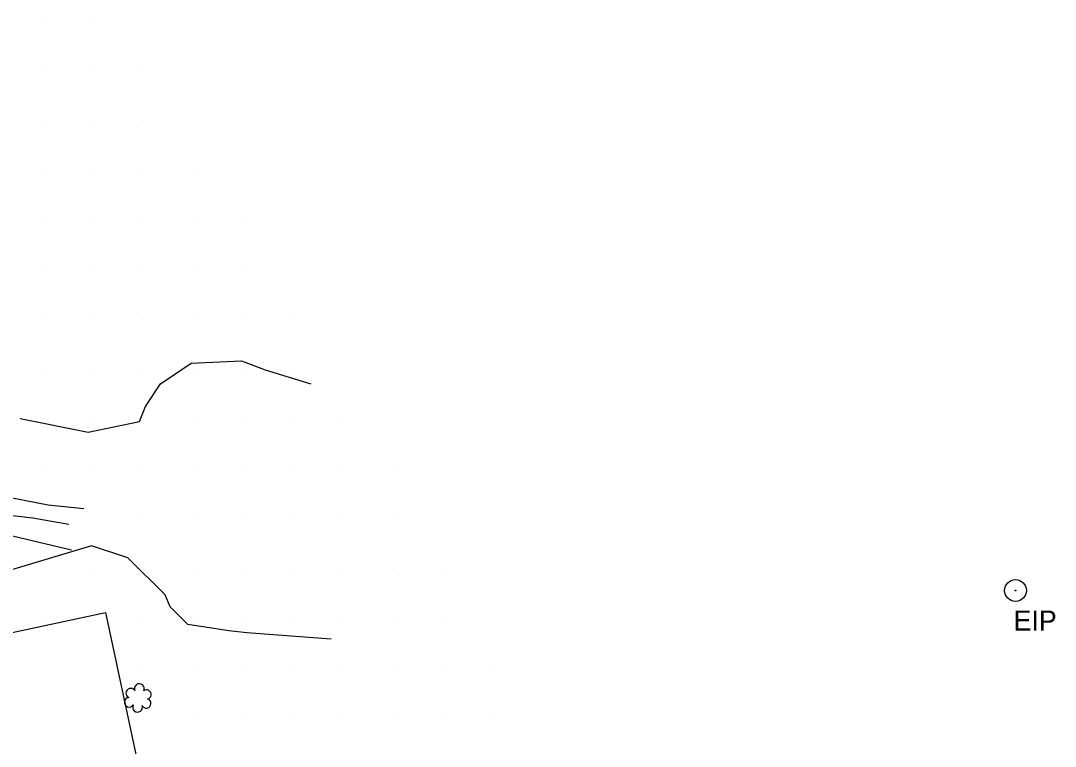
# Model space of a CAD drawing. Extents: x 1548934 to 1561348, y 809680 to 824075.
# Drawn here: x 1552125.4 to 1552333.2, y 810494.3 to 810640 of the extents above; entities that cross this region are included whole.
import ezdxf

# ---------------------------------------------------------------- set-up
doc = ezdxf.new("R2010")
doc.units = 0
for name, color, linetype in [('E_NCDOT_Vertical_Profile_Ground_Line', 7, 'Continuous'), ('Exist Building', 7, 'Continuous'), ('Exist DTM QL2 LIDAR Elevation Point', 7, 'Continuous'), ('Exist Vegetation Shrub CELL', 7, 'Continuous'), ('Exist Vegetation Woods Line', 7, 'Continuous'), ('P_NCDOT_Horizontal_Alignment_Station_Major_Label', 7, 'Continuous'), ('P_NCDOT_Horizontal_Alignment_Tick_Large', 7, 'Continuous'), ('P_NCDOT_Vertical_Profile_Grade_Minor_Road', 7, 'Continuous'), ('PH Exist DTM Breakline', 7, 'Continuous')]:
    doc.layers.add(name, color=color, linetype=linetype)

msp = doc.modelspace()

# ---------------------------------------------------------------- linework, layer by layer
at = {"layer": 'E_NCDOT_Vertical_Profile_Ground_Line'}
for points in [[(1552269.12, 810011.85), (1552259.92, 810023.16), (1552240.77, 810045.39), (1552214.34, 810080.42), (1552187.87, 810115.32), (1552162.13, 810150.99), (1552135.64, 810187.58), (1552109.72, 810225.45), (1552084.15, 810264.06), (1552058.91, 810303.06), (1552035.06, 810342.6), (1552011.64, 810381.93), (1551989.04, 810421.64), (1551966.75, 810462.54), (1551944.7, 810504.81), (1551922.38, 810547.42), (1551904.22, 810585.98), (1551891.94, 810609.51), (1551888.01, 810619.12)], [(1552253.41, 809998.89), (1552244.07, 810010.35), (1552226, 810034.01), (1552199.08, 810069.05), (1552172.73, 810104.35), (1552146.5, 810139.67), (1552120.17, 810176.34), (1552094.24, 810214.53), (1552068.08, 810253.47), (1552042.84, 810293.18), (1552018.16, 810332.72), (1551995.31, 810372.57), (1551972.35, 810412.52), (1551950.07, 810453.78), (1551927.46, 810496.24), (1551905.62, 810539.48), (1551886.94, 810576.33), (1551876.35, 810599.17), (1551872.14, 810607.03)]]:
    msp.add_open_spline(points, degree=3, dxfattribs=at)
at = {"layer": 'Exist Building'}
msp.add_lwpolyline([(1552099.25, 810511.94), (1552142.43, 810521.19), (1552149.46, 810488.38), (1552136.3, 810485.57), (1552141.47, 810461.43), (1552137.51, 810460.58), (1552137.74, 810459.53), (1552129.3, 810457.72), (1552129.07, 810458.77), (1552124.09, 810457.7), (1552124.32, 810456.65), (1552115.66, 810454.8), (1552115.42, 810455.89), (1552111.82, 810455.12), (1552111.61, 810456.08), (1552103.73, 810454.4), (1552092.99, 810504.54), (1552100.49, 810506.15)], close=True, dxfattribs=at)
at = {"layer": 'Exist DTM QL2 LIDAR Elevation Point'}
for p, q in [((1552130.03, 810639.98), (1552130.03, 810639.98)), ((1552140.03, 810639.98), (1552140.03, 810639.98)), ((1552130.03, 810629.98), (1552130.03, 810629.98)), ((1552140.03, 810629.98), (1552140.03, 810629.98)), ((1552150.03, 810629.98), (1552150.03, 810629.98)), ((1552130.03, 810619.98), (1552130.03, 810619.98)), ((1552140.03, 810619.98), (1552140.03, 810619.98)), ((1552150.03, 810619.98), (1552150.03, 810619.98)), ((1552130.03, 810609.98), (1552130.03, 810609.98)), ((1552140.03, 810609.98), (1552140.03, 810609.98)), ((1552150.03, 810609.98), (1552150.03, 810609.98)), ((1552160.03, 810609.98), (1552160.03, 810609.98)), ((1552130.03, 810599.98), (1552130.03, 810599.98)), ((1552140.03, 810599.98), (1552140.03, 810599.98)), ((1552150.03, 810599.98), (1552150.03, 810599.98)), ((1552160.03, 810599.98), (1552160.03, 810599.98)), ((1552170.03, 810599.98), (1552170.03, 810599.98)), ((1552130.03, 810589.98), (1552130.03, 810589.98)), ((1552140.03, 810589.98), (1552140.03, 810589.98)), ((1552150.03, 810589.98), (1552150.03, 810589.98)), ((1552160.03, 810589.98), (1552160.03, 810589.98)), ((1552170.03, 810589.98), (1552170.03, 810589.98)), ((1552130.03, 810579.98), (1552130.03, 810579.98)), ((1552140.03, 810579.98), (1552140.03, 810579.98)), ((1552150.03, 810579.98), (1552150.03, 810579.98)), ((1552160.03, 810579.98), (1552160.03, 810579.98)), ((1552170.03, 810579.98), (1552170.03, 810579.98)), ((1552180.03, 810579.98), (1552180.03, 810579.98)), ((1552130.03, 810569.98), (1552130.03, 810569.98)), ((1552140.03, 810569.98), (1552140.03, 810569.98)), ((1552150.03, 810569.98), (1552150.03, 810569.98)), ((1552160.03, 810569.98), (1552160.03, 810569.98)), ((1552170.03, 810569.98), (1552170.03, 810569.98)), ((1552180.03, 810569.98), (1552180.03, 810569.98)), ((1552130.03, 810559.98), (1552130.03, 810559.98)), ((1552140.03, 810559.98), (1552140.03, 810559.98)), ((1552150.03, 810559.98), (1552150.03, 810559.98)), ((1552160.03, 810559.98), (1552160.03, 810559.98)), ((1552170.03, 810559.98), (1552170.03, 810559.98)), ((1552180.03, 810559.98), (1552180.03, 810559.98)), ((1552190.03, 810559.98), (1552190.03, 810559.98)), ((1552130.03, 810549.97), (1552130.03, 810549.97)), ((1552140.03, 810549.97), (1552140.03, 810549.97)), ((1552150.03, 810549.97), (1552150.03, 810549.97)), ((1552160.03, 810549.97), (1552160.03, 810549.97)), ((1552170.03, 810549.97), (1552170.03, 810549.97)), ((1552180.03, 810549.97), (1552180.03, 810549.97)), ((1552190.03, 810549.97), (1552190.03, 810549.97)), ((1552200.03, 810549.97), (1552200.03, 810549.97)), ((1552150.03, 810539.97), (1552150.03, 810539.97)), ((1552160.03, 810539.97), (1552160.03, 810539.97)), ((1552170.03, 810539.97), (1552170.03, 810539.97)), ((1552180.03, 810539.97), (1552180.03, 810539.97)), ((1552190.03, 810539.97), (1552190.03, 810539.97)), ((1552200.03, 810539.97), (1552200.03, 810539.97)), ((1552140.03, 810529.97), (1552140.03, 810529.97)), ((1552150.03, 810529.97), (1552150.03, 810529.97)), ((1552160.03, 810529.97), (1552160.03, 810529.97)), ((1552170.03, 810529.97), (1552170.03, 810529.97)), ((1552180.03, 810529.97), (1552180.03, 810529.97)), ((1552190.03, 810529.97), (1552190.03, 810529.97)), ((1552200.03, 810529.97), (1552200.03, 810529.97)), ((1552210.04, 810529.97), (1552210.04, 810529.97)), ((1552130.03, 810519.97), (1552130.03, 810519.97)), ((1552150.03, 810519.97), (1552150.03, 810519.97)), ((1552160.03, 810519.97), (1552160.03, 810519.97)), ((1552170.03, 810519.97), (1552170.03, 810519.97)), ((1552180.03, 810519.97), (1552180.03, 810519.97)), ((1552190.03, 810519.97), (1552190.03, 810519.97)), ((1552200.03, 810519.97), (1552200.03, 810519.97)), ((1552210.04, 810519.97), (1552210.04, 810519.97)), ((1552150.03, 810509.97), (1552150.03, 810509.97)), ((1552160.03, 810509.97), (1552160.03, 810509.97)), ((1552170.03, 810509.97), (1552170.03, 810509.97)), ((1552180.03, 810509.97), (1552180.03, 810509.97)), ((1552190.03, 810509.97), (1552190.03, 810509.97)), ((1552200.03, 810509.97), (1552200.03, 810509.97)), ((1552210.04, 810509.97), (1552210.04, 810509.97)), ((1552220.04, 810509.97), (1552220.04, 810509.97)), ((1552150.03, 810499.97), (1552150.03, 810499.97)), ((1552160.03, 810499.97), (1552160.03, 810499.97)), ((1552170.03, 810499.97), (1552170.03, 810499.97)), ((1552180.03, 810499.97), (1552180.03, 810499.97)), ((1552190.03, 810499.97), (1552190.03, 810499.97)), ((1552200.03, 810499.97), (1552200.03, 810499.97)), ((1552210.04, 810499.97), (1552210.04, 810499.97)), ((1552220.04, 810499.97), (1552220.04, 810499.97))]:
    msp.add_line(p, q, dxfattribs=at)
at = {"layer": 'Exist Vegetation Shrub CELL'}
msp.add_line((1552148.98, 810503.88), (1552148.98, 810503.88), dxfattribs=at)
for centre, radius, start, end in [((1552149.21, 810505.92), 0.99, 334.8391, 200.4717), ((1552147.49, 810505.01), 0.968, 35.8908, 245.4216), ((1552150.65, 810504.75), 0.929, 284.4567, 126.0861), ((1552147.18, 810503.18), 0.955, 95.1099, 327.9534), ((1552148.85, 810502.2), 0.984, 151.2797, 21.387), ((1552150.61, 810502.95), 0.937, 204.9913, 73.4601)]:
    msp.add_arc(centre, radius, start, end, dxfattribs=at)
at = {"layer": 'Exist Vegetation Woods Line'}
for points in [[(1552125.26, 810560.17), (1552138.9, 810557.41), (1552149.24, 810559.54), (1552150.42, 810562.56), (1552153.48, 810567.12), (1552159.64, 810571.22), (1552169.71, 810571.69), (1552174.5, 810569.93), (1552183.65, 810567.13)], [(1552187.72, 810515.86), (1552170.8, 810517.11), (1552167.18, 810517.55), (1552158.93, 810518.77), (1552155.4, 810522.36), (1552154.37, 810524.77), (1552146.87, 810532.15), (1552139.59, 810534.59), (1552090.86, 810519.98)]]:
    msp.add_lwpolyline(points, dxfattribs=at)
at = {"layer": 'P_NCDOT_Horizontal_Alignment_Tick_Large'}
for radius in [2.2, 0.0707]:
    msp.add_circle((1552325.16, 810525.62), radius, dxfattribs=at)
at = {"layer": 'P_NCDOT_Vertical_Profile_Grade_Minor_Road'}
msp.add_open_spline([(1551879.82, 810614.21), (1551884.04, 810605.38), (1551895.16, 810581.81), (1551913.82, 810543.91), (1551935.87, 810500.72), (1551958.31, 810458.4), (1551980.95, 810417.47), (1552003.45, 810377.53), (1552026.54, 810337.94), (1552050.88, 810298.39), (1552075.93, 810258.79), (1552101.83, 810219.9), (1552127.9, 810181.92), (1552154.01, 810145.19), (1552180.07, 810109.84), (1552206.52, 810074.71), (1552233.37, 810039.85), (1552251.61, 810016.53), (1552260.84, 810005.28)], degree=3, dxfattribs=at)
at = {"layer": 'PH Exist DTM Breakline'}
for points in [[(1552135.06, 810538.88), (1552127.83, 810540.15), (1552122.56, 810540.74), (1552116.4, 810541.01), (1552111.55, 810540.67), (1552108.08, 810540.06), (1552104.92, 810539.51), (1552106.2, 810541.32), (1552107.04, 810541.98), (1552108.27, 810542.82), (1552109.54, 810543.54), (1552115.44, 810544.21), (1552123.68, 810544.24), (1552130.92, 810542.83), (1552138.05, 810542.05)], [(1552135.57, 810533.68), (1552122.63, 810536.77), (1552116, 810536.87), (1552111.15, 810536.76), (1552107.01, 810537.03), (1552105.37, 810537.75), (1552104.92, 810539.51)]]:
    msp.add_lwpolyline(points, dxfattribs=at)

# ---------------------------------------------------------------- texts
at = {"layer": 'P_NCDOT_Horizontal_Alignment_Station_Major_Label'}
msp.add_text('EIP', height=4.02, dxfattribs=at).set_placement((1552324.77, 810517.58))

doc.saveas('drawing.dxf')
